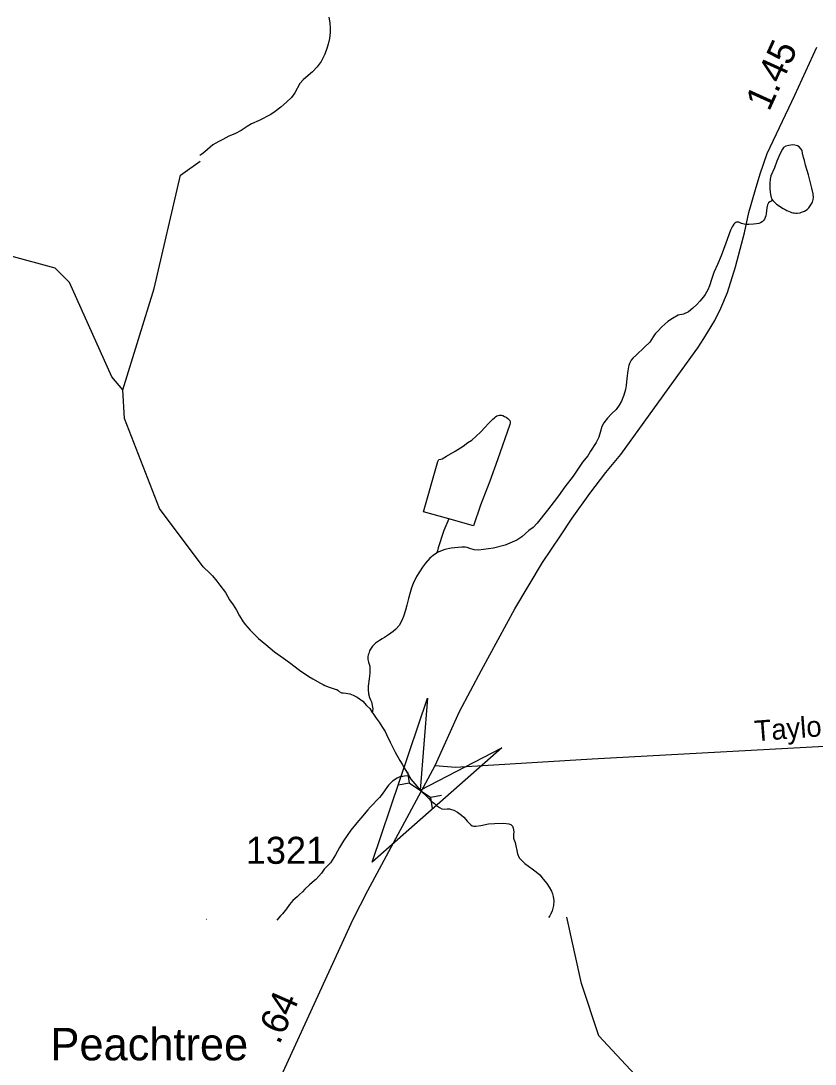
# Model space of a CAD drawing. Extents: x 2220236 to 2384410, y 720751 to 894131.
# Drawn here: x 2258046 to 2261721, y 819432 to 824260 of the extents above; entities that cross this region are included whole.
import ezdxf

# ---------------------------------------------------------------- set-up
doc = ezdxf.new("R2010")
doc.units = 0
for name, color, linetype in [('Exist Cultural Church with Cemetery Label', 7, 'Continuous'), ('Exist Hydrographic Creek Single Shore', 7, 'Continuous'), ('Exist Hydrographic Misc Water Feature', 7, 'Continuous'), ('Exist Hydrographic Pond Under 1500 Sq Ft', 7, 'Continuous'), ('Exist Road Secondary Mileage Hundredths English Label', 7, 'Continuous'), ('Exist Road Secondary Structure Culvert Attributed CELL', 7, 'Continuous'), ('Exist Road Secondary Structure Culvert CELL', 7, 'Continuous'), ('Exist Road Secondary Type 51 Attributed', 7, 'Continuous'), ('Exist Road Secondary Type 51 Label', 7, 'Continuous'), ('Exist Road Secondary Type 51 Number Label', 7, 'Continuous')]:
    doc.layers.add(name, color=color, linetype=linetype)

msp = doc.modelspace()

# ---------------------------------------------------------------- linework, layer by layer
at = {"layer": 'Exist Hydrographic Creek Single Shore'}
for points in [[(2258516.9, 822551.9), (2258466.9, 822612), (2258270.8, 823049.1), (2258203.8, 823116), (2257994.8, 823172.8), (2257927.8, 823321.8), (2257942.8, 823505.2), (2257998.7, 823756.6), (2257988.9, 823996.3), (2257894.8, 824214.7), (2257776.9, 824361.5), (2257640.7, 824771.1), (2257606.9, 824886.5), (2257595.8, 825162.3), (2257560.7, 825336.8), (2257557.9, 825694.4), (2257523.8, 825777.1), (2257406.7, 825907.5), (2256941.1, 826169.1)], [(2267515, 817093.5), (2267266.1, 817049.5), (2267007.1, 817064.6), (2266826, 817057.6), (2266603.3, 817033.5), (2266206.2, 817003.4), (2265193, 816921.8), (2264491.1, 817182.3), (2264233.2, 817148.3), (2264059.1, 817063.3), (2263859.1, 817077.3), (2263558.1, 817181.9), (2263321.1, 817547.6), (2263104.1, 817637.4), (2262619, 817798.3), (2262368, 817944.5), (2261546.2, 818545.4), (2261336, 818726.8), (2261260.1, 818885.8), (2261125, 819033), (2261074.1, 819181.6), (2260720, 819562.8), (2260639.4, 819805.1), (2260572.4, 820111)]]:
    msp.add_lwpolyline(points, dxfattribs=at)
at = {"layer": 'Exist Hydrographic Misc Water Feature'}
msp.add_line((2258905.8, 820100.2), (2258904.9, 820100.2), dxfattribs=at)
for points in [[(2259470.8, 824276.7), (2259474.9, 824251), (2259477, 824226.4), (2259477.5, 824206.7), (2259473.7, 824178.9), (2259467.9, 824152.8), (2259461.9, 824132.5), (2259451.8, 824106.5), (2259434.7, 824072.4), (2259416.9, 824048.2), (2259395, 824024.1), (2259365, 823997.4), (2259351.3, 823987.2), (2259337.2, 823971.1), (2259313.7, 823927.3), (2259298.1, 823905.4), (2259275, 823883.9), (2259248.6, 823860.5), (2259222.7, 823840.7), (2259203, 823826.3), (2259149, 823799.5), (2259113.6, 823783.9), (2259093.3, 823771.2), (2259065.7, 823752.7), (2259035.8, 823736.9), (2259007.7, 823726), (2258980.2, 823711.8), (2258962, 823701.7), (2258934.4, 823685.9), (2258896.4, 823653.9), (2258882.7, 823643.3), (2258874, 823637)], [(2258516.9, 822551.9), (2258662.9, 823021.3), (2258783.9, 823546.8), (2258874.9, 823610.3)], [(2261525.2, 823428.9), (2261520.3, 823427.4), (2261515.3, 823424.9), (2261511.3, 823423.3), (2261505.6, 823418.5), (2261503.6, 823415.3), (2261501.2, 823408.7), (2261499.4, 823403.2), (2261497.9, 823395), (2261495.7, 823381), (2261494.1, 823367.2), (2261492.9, 823358.1), (2261490.1, 823350.9), (2261486, 823342.8), (2261482.3, 823337), (2261476.6, 823330.5), (2261467.6, 823325.1), (2261460.4, 823322.7), (2261450.2, 823320.6), (2261436.4, 823319.2), (2261414.4, 823318), (2261398.6, 823318.4), (2261386.2, 823320.3), (2261380.3, 823322), (2261368.3, 823327.9), (2261366.4, 823328.9), (2261362.8, 823329), (2261357.5, 823329.1), (2261354.2, 823327.5), (2261348.9, 823324.3), (2261344.5, 823319.5), (2261336.7, 823307.2), (2261328.9, 823291.9), (2261307.3, 823231.7), (2261285.7, 823173.1), (2261268.5, 823133.1), (2261252.3, 823095.1), (2261240.8, 823062.5), (2261231.7, 823033.8), (2261224.4, 823015.3), (2261211.5, 822994.2), (2261204.4, 822982.9), (2261187.6, 822962.6), (2261173.8, 822948.1), (2261154.7, 822929.8), (2261134.4, 822913.8), (2261112.5, 822903.5), (2261086.5, 822897.4), (2261060.6, 822883.2), (2261039, 822868.9), (2261011.3, 822844.2), (2260993.1, 822823.9), (2260981.4, 822812), (2260971.3, 822798.1), (2260955.7, 822773.9), (2260931.9, 822749.8), (2260892.8, 822712.9), (2260877.1, 822698.4), (2260870.3, 822689.7), (2260862.1, 822674.1), (2260858.3, 822665.3), (2260856.9, 822659.5), (2260854.9, 822640.8), (2260853, 822631), (2260851.1, 822615.3), (2260849.9, 822604.8), (2260845.9, 822572.1), (2260843.6, 822554.8), (2260835.8, 822527.1), (2260824.7, 822499.4), (2260814.5, 822480.9), (2260800.7, 822462.2), (2260778.9, 822440.7), (2260760.8, 822422), (2260743, 822400.4), (2260734.1, 822382.6), (2260725.6, 822355.5), (2260719.9, 822333.6), (2260708.3, 822308.3), (2260682.2, 822268.8), (2260668.6, 822247.8), (2260645, 822217.1), (2260601.7, 822153.1), (2260563, 822103), (2260534.2, 822062), (2260512.7, 822036.2), (2260483, 821995.8), (2260435.5, 821935.1), (2260415.7, 821915.2), (2260395.8, 821900.8), (2260364, 821872.6), (2260340.4, 821856.1), (2260286.8, 821833.2), (2260232.7, 821819.6), (2260186.7, 821813.3), (2260163.6, 821810.5), (2260143, 821812.6)], [(2258889.9, 821734), (2258687.7, 822003.9), (2258525.7, 822420.6), (2258516.9, 822551.9)], [(2260025.3, 821955.1), (2260003.5, 821900.8), (2259992.3, 821868.8), (2259985.7, 821849.3), (2259976.9, 821820.9), (2259973, 821806.9), (2259970.9, 821798.1)], [(2260143, 821812.6), (2260122.8, 821818.6), (2260111.1, 821822.1), (2260100.9, 821824), (2260086.5, 821824.2), (2260037.2, 821819.7), (2260006.9, 821813.8), (2259979.2, 821802.9), (2259970.9, 821798.1)], [(2259970.9, 821798.1), (2259969.2, 821797.2), (2259953.2, 821785.4), (2259938.5, 821773.2), (2259917.7, 821750), (2259903.6, 821732.3), (2259876.1, 821688.5), (2259861.3, 821656.7), (2259852.7, 821635.6), (2259847, 821613.7), (2259839.2, 821586), (2259831.4, 821555.6), (2259825, 821532.2), (2259815.8, 821503.5), (2259808.9, 821484.9), (2259796.3, 821462.2), (2259781.2, 821445.2), (2259768.5, 821433.3), (2259746.5, 821419), (2259728.9, 821406.9), (2259717, 821400.6), (2259704.7, 821392.6), (2259686.7, 821379.2), (2259672.9, 821366.4), (2259663.5, 821352.5), (2259659.4, 821344.4), (2259655.2, 821332.3), (2259653.4, 821326.4), (2259651.6, 821316), (2259651.7, 821304.5), (2259654, 821292), (2259657.8, 821282.1), (2259660.2, 821273.8), (2259661, 821264), (2259659.9, 821242.7), (2259658.3, 821227.9), (2259656.7, 821214.2), (2259653, 821180.5), (2259652.9, 821173.9), (2259652.8, 821170), (2259653.1, 821165.7), (2259654.3, 821146), (2259659.2, 821127.9), (2259663.5, 821118), (2259667.6, 821108), (2259671.5, 821092.5), (2259673.6, 821082.6), (2259673.9, 821078.4), (2259672.9, 821063.6), (2259671.9, 821059.7)], [(2258891.5, 821731.7), (2258889.9, 821734)], [(2258890.7, 821732.6), (2258892.3, 821730.9), (2258916.4, 821707.4), (2258932.5, 821691.7), (2258952.7, 821667.3), (2258967, 821648.3), (2258993.2, 821614), (2259011.5, 821580.2), (2259027.5, 821556.9), (2259044, 821532.6), (2259058.2, 821507), (2259074.4, 821478.8), (2259084.6, 821464.5), (2259107, 821439.4), (2259144.9, 821401.9), (2259179.5, 821374), (2259219.8, 821340.3), (2259261.8, 821310.9), (2259288.3, 821290.7), (2259334.5, 821255.3), (2259378.8, 821225.5), (2259396.6, 821215.3), (2259431.6, 821194.9), (2259444.9, 821188.1), (2259452.7, 821184), (2259472.9, 821176), (2259491.1, 821170.7), (2259499.6, 821167.3), (2259507.1, 821164.8), (2259513.9, 821160.4), (2259519, 821157), (2259529.7, 821150.2), (2259537.3, 821149.4), (2259549.7, 821149.2), (2259559.2, 821147.3), (2259567.4, 821145.5), (2259583.3, 821139.3), (2259601.5, 821130.7), (2259627.7, 821112.1), (2259645.6, 821092.1), (2259659.8, 821078), (2259671.9, 821059.7)], [(2259671.9, 821059.7), (2259673.8, 821056.4), (2259690, 821032.1), (2259704.4, 821014.8), (2259718.6, 820988.9), (2259730.7, 820970.6), (2259737, 820956.7), (2259754.9, 820922.5), (2259777.6, 820875.5), (2259799.8, 820837.3), (2259810.2, 820819.7), (2259820, 820803.1), (2259838.7, 820769.9), (2259840.9, 820765.9)], [(2259840.9, 820765.9), (2259820.5, 820763.7), (2259812.7, 820763.3), (2259806.4, 820763.4), (2259798.8, 820760.9), (2259786.6, 820755.6), (2259765, 820741.3), (2259746.9, 820722.6), (2259713.4, 820675.1), (2259705.4, 820666.1), (2259663.8, 820622), (2259652, 820608.1), (2259618.4, 820569.5), (2259608.7, 820557.5), (2259594.5, 820541.4), (2259572.3, 820514.7), (2259538.5, 820464.5), (2259519.8, 820434.7), (2259502.1, 820400.7), (2259478.7, 820362.5), (2259460.6, 820344.1), (2259449.9, 820333.5), (2259437, 820315.8), (2259424.9, 820302.2), (2259411.2, 820286.1), (2259405.2, 820282), (2259381.4, 820261.1), (2259359.7, 820241.3), (2259349.6, 820229), (2259335.2, 820216.2), (2259323.9, 820206.6), (2259303.9, 820189), (2259288.4, 820170.6), (2259274.5, 820150.2), (2259268.8, 820142.1), (2259256, 820127), (2259246.9, 820117.3), (2259229.8, 820098)], [(2259840.9, 820765.9), (2259850.4, 820750), (2259878.6, 820718.3), (2259892.7, 820699.7), (2259931.3, 820662.4), (2259943.5, 820650.7), (2259959, 820637.2), (2259968.6, 820628.8), (2259983.2, 820619.3), (2259993.9, 820613.5), (2260004, 820611.7), (2260017.8, 820613), (2260029.3, 820612.8), (2260038.8, 820610), (2260049.9, 820607.5), (2260066.4, 820597.3), (2260084.8, 820583.8), (2260096.1, 820574.4), (2260104.4, 820564.3), (2260110.5, 820556), (2260126.5, 820540.3), (2260134.6, 820534.2), (2260142.4, 820532.4), (2260150.6, 820532.2), (2260173.7, 820536.7), (2260210.2, 820543.5), (2260237.8, 820545.2), (2260280.5, 820546.9), (2260304.4, 820543.8), (2260312.8, 820540.4), (2260320.6, 820533.6), (2260324, 820523.1), (2260326.6, 820506.6), (2260325.7, 820495.2), (2260324.9, 820488.6), (2260324.7, 820477.8), (2260327.2, 820472.2), (2260332.8, 820457.3), (2260343.5, 820404.6), (2260352, 820386.4), (2260378, 820360.2), (2260411.9, 820334.9), (2260430.3, 820321.4), (2260446.4, 820307.3), (2260462.4, 820287.3), (2260479.1, 820267.3), (2260490.9, 820251.3), (2260501.3, 820231.4), (2260505.3, 820219.8), (2260509.3, 820207.6), (2260511.9, 820187.9), (2260510.4, 820165.6), (2260504.7, 820141.1), (2260498.1, 820127.5), (2260493, 820118.4), (2260486.6, 820110.4)]]:
    msp.add_lwpolyline(points, dxfattribs=at)
at = {"layer": 'Exist Hydrographic Pond Under 1500 Sq Ft'}
for points in [[(2261525.2, 823428.9), (2261541.6, 823411.2), (2261573.6, 823391.8), (2261581.8, 823387.4), (2261590.2, 823382.3), (2261597.7, 823378.9), (2261605.8, 823376.4), (2261612, 823373.6), (2261617.8, 823371.9), (2261624.1, 823371.1), (2261632.2, 823370), (2261637.8, 823369.8), (2261652, 823372.2), (2261658.6, 823374.3), (2261671.8, 823379), (2261683.8, 823386.9), (2261691.8, 823395), (2261701.6, 823408.9), (2261708.1, 823421.8), (2261711.3, 823433.3), (2261713.1, 823443.1), (2261711.2, 823460.2), (2261705.5, 823486.5), (2261690.3, 823546.9), (2261675.9, 823593.1), (2261671.1, 823613.5), (2261667.7, 823627.7), (2261663.2, 823648.1), (2261660.5, 823659.6), (2261657.1, 823666.3), (2261647.1, 823678), (2261639, 823682.4), (2261627.6, 823684.3), (2261617.1, 823686.1), (2261607.9, 823684.7), (2261599, 823683.9), (2261584.9, 823680.2), (2261574.9, 823673.9), (2261569.2, 823665.8), (2261557.5, 823643.7), (2261543.8, 823611.2), (2261532.3, 823580.3), (2261516.4, 823542.9), (2261512.5, 823527.6), (2261512.4, 823525), (2261511.9, 823512.8), (2261510.7, 823503), (2261510.8, 823493.2), (2261510.9, 823483.3), (2261512.3, 823468.5), (2261514.3, 823457), (2261517.3, 823442.9), (2261519.2, 823437.2), (2261525.2, 823428.9)], [(2260025.3, 821955.1), (2259909.5, 821988.6), (2259975, 822221.1), (2259979.1, 822229.3), (2259989, 822231.4), (2259994.9, 822232.9), (2260014.9, 822245.6), (2260054.7, 822269.4), (2260092.3, 822292.5), (2260114.6, 822308.5), (2260132.2, 822320.2), (2260172.3, 822357.1), (2260193.5, 822379), (2260208.5, 822395.1), (2260223.3, 822410.2), (2260230, 822416.6), (2260237, 822423), (2260241.7, 822427.8), (2260248.3, 822432), (2260253.6, 822434.2), (2260261.2, 822435.6), (2260269.1, 822434.8), (2260276.2, 822433), (2260283.7, 822429.6), (2260291.2, 822426.2), (2260299.3, 822420.1), (2260305.4, 822414.4), (2260308.9, 822410.1), (2260310.1, 822404.5), (2260310, 822397.9), (2260308.2, 822392), (2260250.7, 822229.2), (2260215.8, 822129.2), (2260172.9, 822018.6), (2260139.7, 821922.5), (2260025.3, 821955.1)]]:
    msp.add_lwpolyline(points, dxfattribs=at)
at = {"layer": 'Exist Road Secondary Structure Culvert Attributed CELL'}
msp.add_lwpolyline([(2260271.6, 820895.3), (2259671.1, 820366.7), (2259926.8, 821124.7), (2259892.7, 820699.7)], close=True, dxfattribs=at)
at = {"layer": 'Exist Road Secondary Structure Culvert CELL'}
for p, q in [((2259835.4, 820784.4), (2259843, 820734.2)), ((2259793.3, 820723.8), (2259843, 820734.2)), ((2259843, 820734.2), (2259942.3, 820665.2)), ((2259992, 820675.6), (2259942.3, 820665.2)), ((2259950, 820615), (2259942.3, 820665.2))]:
    msp.add_line(p, q, dxfattribs=at)
at = {"layer": 'Exist Road Secondary Type 51 Attributed'}
for points in [[(2259962.3, 820814.3), (2260076.1, 821063), (2260177.3, 821255.1), (2260331.8, 821538.6), (2260459.7, 821753.2), (2260542.3, 821877.2), (2260597.4, 821957.9), (2260678, 822072.1), (2260752.8, 822170.6), (2260821.7, 822253.2), (2261125.6, 822674.5), (2261178.7, 822747.4), (2261206.3, 822790.7), (2261256.5, 822873.4), (2261284, 822930.5), (2261315.5, 823003.3), (2261352.9, 823121.4), (2261374.5, 823204.1), (2261394.2, 823278.9), (2261414.8, 823373.4), (2261444.4, 823479.7), (2261466, 823552.6), (2261499.4, 823647.1), (2261626.3, 823916.8), (2261728.8, 824139.2)], [(2259962.3, 820814.3), (2260057, 820806.7), (2260689.7, 820844.6), (2261933.6, 820912.8), (2262186.1, 820925.5), (2262489.2, 820948.2), (2262807.9, 820962.7), (2263454, 821001.3), (2263713.1, 821013.3), (2264052.8, 821030.4), (2264252.4, 821044.3), (2264438.9, 821056.9), (2264535.2, 821072.3), (2264596.6, 821087.9), (2264649.8, 821097.3), (2264707.7, 821112.6), (2264778.6, 821132.7)], [(2258724.2, 817770.1), (2258744.2, 817942.3), (2258762.5, 818073.7), (2258851.5, 818416.9), (2259139.6, 819133.7), (2259583.3, 820102.9), (2259652, 820235.4), (2259962.3, 820814.3)]]:
    msp.add_lwpolyline(points, dxfattribs=at)

# ---------------------------------------------------------------- texts
at = {"layer": 'Exist Cultural Church with Cemetery Label'}
msp.add_text('Peachtree', height=150, dxfattribs=at).set_placement((2258183.1, 819449.1))
at = {"layer": 'Exist Road Secondary Mileage Hundredths English Label'}
for s, rotation, p in [('1.45', 65.5988, (2261507.9, 823837.3)), ('.64', 66.2412, (2259241.4, 819518.3))]:
    msp.add_text(s, height=125, rotation=rotation, dxfattribs=at).set_placement(p)
at = {"layer": 'Exist Road Secondary Type 51 Label'}
msp.add_text("Taylor's", height=95, rotation=4.2986, dxfattribs=at).set_placement((2261444, 820926.1))
at = {"layer": 'Exist Road Secondary Type 51 Number Label'}
msp.add_text('1321', height=125, dxfattribs=at).set_placement((2259086.5, 820358.7))

doc.saveas('drawing.dxf')
